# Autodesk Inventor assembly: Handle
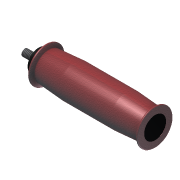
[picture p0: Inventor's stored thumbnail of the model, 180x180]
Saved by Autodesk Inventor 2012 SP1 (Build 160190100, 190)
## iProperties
Created: 2005-12
Part Number: Handle
Document SubType Name: Assembly
Designer: t_munrn
Author: t_munrn
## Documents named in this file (4)
- D:\AOTC\Autodesk Inventor 2012 Essential for New Users\Autodesk Inventor 2012 Essentials - Project Files\Learning\Workspace\Sub-Assemblies\Handle1.iam
- D:\AOTC\Autodesk Inventor 2012 Essential for New Users\Autodesk Inventor 2012 Essentials - Project Files\Learning\Workspace\Parts\GP-103.ipt
- D:\AOTC\Autodesk Inventor 2012 Essential for New Users\Autodesk Inventor 2012 Essentials - Project Files\Learning\Workspace\Parts\HANDLE.ipt
- D:\AOTC\Autodesk Inventor 2012 Essential for New Users\Autodesk Inventor 2012 Essentials - Project Files\Learning\Workspace\Parts\stud.ipt
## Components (3 placed, 3 different names)
1. GP-103:1 — Mate:4, Flush:1
2. HANDLE:1 — Mate:1, Mate:2, Mate:3, Mate:4, Flush:1
3. stud:1 — Mate:1, Mate:2, Mate:3
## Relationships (5: Mate 4, Flush 1)
- Mate:1: HANDLE:1 ↔ stud:1
- Mate:2: HANDLE:1 ↔ stud:1
- Mate:3: HANDLE:1 ↔ stud:1
- Mate:4: GP-103:1 ↔ HANDLE:1
- Flush:1: GP-103:1 ↔ HANDLE:1
